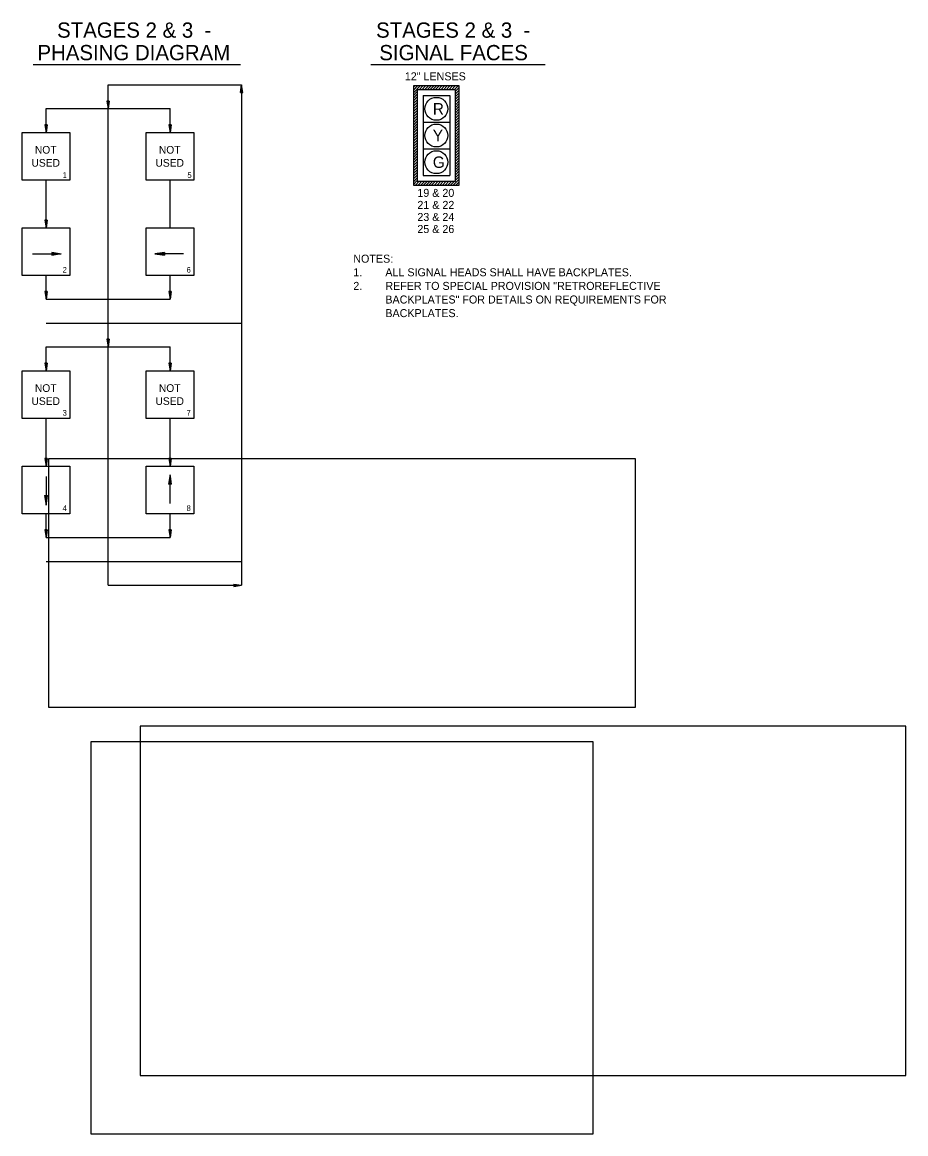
# Model space of a CAD drawing. Extents: x 418532 to 419834, y -565899 to -565282.
# Drawn here: x 418893 to 419356, y -565865 to -565282 of the extents above; entities that cross this region are included whole.
import ezdxf

# ---------------------------------------------------------------- set-up
doc = ezdxf.new("R2010")
doc.units = 0
for name, color, linetype in [('C-ANNO-TEXT', 7, 'Continuous'), ('Level 57', 7, 'Continuous'), ('Level 61', 7, 'Continuous'), ('T_Drafting', 7, 'Continuous'), ('Template', 7, 'Continuous'), ('V-SIGNAL-LOOP', 7, 'Continuous')]:
    doc.layers.add(name, color=color, linetype=linetype)

msp = doc.modelspace()

# ---------------------------------------------------------------- linework, layer by layer
at = {"layer": 'Level 57'}
for p, q in [((418898.43, -565304.08), (419007.1, -565304.08)), ((419075.35, -565304.08), (419166.69, -565304.08)), ((418937.63, -565577.29), (418937.63, -565314.79)), ((418937.63, -565314.79), (419007.63, -565314.79)), ((419007.03, -565318.79), (419007.63, -565314.79)), ((419007.63, -565314.79), (419007.63, -565577.29)), ((419008.23, -565318.79), (419007.63, -565314.79)), ((419007.03, -565318.79), (419008.23, -565318.79)), ((419007.13, -565318.79), (419007.63, -565315.46)), ((419007.23, -565318.79), (419007.63, -565316.15)), ((419007.33, -565318.79), (419007.63, -565316.81)), ((419007.43, -565318.79), (419007.63, -565317.49)), ((419007.53, -565318.79), (419007.63, -565318.16)), ((419008.13, -565318.79), (419007.63, -565315.46)), ((419008.02, -565318.79), (419007.63, -565316.15)), ((419007.92, -565318.79), (419007.63, -565316.81)), ((419007.82, -565318.79), (419007.63, -565317.49)), ((419007.72, -565318.79), (419007.63, -565318.16)), ((418937.03, -565323.29), (418937.63, -565327.29)), ((418938.23, -565323.29), (418937.03, -565323.29)), ((418937.13, -565323.29), (418937.63, -565326.62)), ((418937.23, -565323.29), (418937.63, -565325.94)), ((418937.33, -565323.29), (418937.63, -565325.27)), ((418937.43, -565323.29), (418937.63, -565324.59)), ((418937.53, -565323.29), (418937.63, -565323.92)), ((418938.23, -565323.29), (418937.63, -565327.29)), ((418937.82, -565323.29), (418937.63, -565324.59)), ((418938.02, -565323.29), (418937.63, -565325.94)), ((418938.13, -565323.29), (418937.63, -565326.62)), ((418937.92, -565323.29), (418937.63, -565325.27)), ((418937.72, -565323.29), (418937.63, -565323.92)), ((418905.13, -565339.79), (418905.13, -565327.29)), ((418905.13, -565327.29), (418970.13, -565327.29)), ((418970.13, -565339.79), (418970.13, -565327.29)), ((418904.53, -565335.79), (418905.13, -565339.79)), ((418905.73, -565335.79), (418904.53, -565335.79)), ((418904.63, -565335.79), (418905.13, -565339.12)), ((418904.73, -565335.79), (418905.13, -565338.44)), ((418904.83, -565335.79), (418905.13, -565337.77)), ((418904.93, -565335.79), (418905.13, -565337.09)), ((418905.03, -565335.79), (418905.13, -565336.42)), ((418905.73, -565335.79), (418905.13, -565339.79)), ((418905.32, -565335.79), (418905.13, -565337.09)), ((418905.52, -565335.79), (418905.13, -565338.44)), ((418905.63, -565335.79), (418905.13, -565339.12)), ((418905.42, -565335.79), (418905.13, -565337.77)), ((418905.22, -565335.79), (418905.13, -565336.42)), ((418969.53, -565335.79), (418970.13, -565339.79)), ((418970.73, -565335.79), (418969.53, -565335.79)), ((418969.63, -565335.79), (418970.13, -565339.12)), ((418969.73, -565335.79), (418970.13, -565338.44)), ((418969.83, -565335.79), (418970.13, -565337.77)), ((418969.93, -565335.79), (418970.13, -565337.09)), ((418970.03, -565335.79), (418970.13, -565336.42)), ((418970.73, -565335.79), (418970.13, -565339.79)), ((418970.32, -565335.79), (418970.13, -565337.09)), ((418970.52, -565335.79), (418970.13, -565338.44)), ((418970.63, -565335.79), (418970.13, -565339.12)), ((418970.42, -565335.79), (418970.13, -565337.77)), ((418970.22, -565335.79), (418970.13, -565336.42)), ((418905.13, -565389.79), (418905.13, -565364.79)), ((418970.13, -565389.79), (418970.13, -565364.79)), ((418904.53, -565385.79), (418905.13, -565389.79)), ((418905.73, -565385.79), (418904.53, -565385.79)), ((418904.63, -565385.79), (418905.13, -565389.12)), ((418904.73, -565385.79), (418905.13, -565388.44)), ((418904.83, -565385.79), (418905.13, -565387.77)), ((418904.93, -565385.79), (418905.13, -565387.09)), ((418905.03, -565385.79), (418905.13, -565386.42)), ((418905.73, -565385.79), (418905.13, -565389.79)), ((418905.32, -565385.79), (418905.13, -565387.09)), ((418905.52, -565385.79), (418905.13, -565388.44)), ((418905.63, -565385.79), (418905.13, -565389.12)), ((418905.42, -565385.79), (418905.13, -565387.77)), ((418905.22, -565385.79), (418905.13, -565386.42)), ((418898.06, -565403.45), (418913.06, -565403.46)), ((418908.06, -565402.71), (418913.06, -565403.46)), ((418908.06, -565402.71), (418908.06, -565404.21)), ((418912.23, -565403.46), (418908.06, -565402.83)), ((418908.06, -565402.96), (418911.37, -565403.46)), ((418910.54, -565403.46), (418908.06, -565403.09)), ((418908.06, -565403.22), (418909.69, -565403.46)), ((418908.85, -565403.46), (418908.06, -565403.34)), ((418913.06, -565403.46), (418908.06, -565404.21)), ((418908.06, -565404.08), (418912.23, -565403.46)), ((418911.37, -565403.46), (418908.06, -565403.96)), ((418908.06, -565403.83), (418910.54, -565403.46)), ((418909.69, -565403.46), (418908.06, -565403.7)), ((418908.06, -565403.58), (418908.85, -565403.46)), ((418967.19, -565402.71), (418962.19, -565403.46)), ((418977.19, -565403.45), (418962.19, -565403.46)), ((418962.19, -565403.46), (418967.19, -565404.21)), ((418963.02, -565403.46), (418967.19, -565402.83)), ((418967.19, -565404.08), (418963.02, -565403.46)), ((418967.19, -565402.96), (418963.88, -565403.46)), ((418963.88, -565403.46), (418967.19, -565403.96)), ((418964.72, -565403.46), (418967.19, -565403.09)), ((418967.19, -565403.83), (418964.72, -565403.46)), ((418967.19, -565403.22), (418965.56, -565403.46)), ((418965.56, -565403.46), (418967.19, -565403.7)), ((418966.4, -565403.46), (418967.19, -565403.34)), ((418967.19, -565403.58), (418966.4, -565403.46)), ((418967.19, -565402.71), (418967.19, -565404.21)), ((418905.13, -565427.29), (418905.13, -565414.79)), ((418970.13, -565427.29), (418970.13, -565414.79)), ((418970.13, -565427.29), (418970.13, -565414.79)), ((418904.53, -565423.29), (418905.13, -565427.29)), ((418905.73, -565423.29), (418904.53, -565423.29)), ((418904.63, -565423.29), (418905.13, -565426.62)), ((418904.73, -565423.29), (418905.13, -565425.94)), ((418904.83, -565423.29), (418905.13, -565425.27)), ((418904.93, -565423.29), (418905.13, -565424.59)), ((418905.03, -565423.29), (418905.13, -565423.92)), ((418905.73, -565423.29), (418905.13, -565427.29)), ((418905.32, -565423.29), (418905.13, -565424.59)), ((418905.52, -565423.29), (418905.13, -565425.94)), ((418905.63, -565423.29), (418905.13, -565426.62)), ((418905.42, -565423.29), (418905.13, -565425.27)), ((418905.22, -565423.29), (418905.13, -565423.92)), ((418969.53, -565423.29), (418970.13, -565427.29)), ((418970.73, -565423.29), (418969.53, -565423.29)), ((418969.53, -565423.29), (418970.13, -565427.29)), ((418970.73, -565423.29), (418969.53, -565423.29)), ((418969.63, -565423.29), (418970.13, -565426.62)), ((418969.63, -565423.29), (418970.13, -565426.62)), ((418969.73, -565423.29), (418970.13, -565425.94)), ((418969.73, -565423.29), (418970.13, -565425.94)), ((418969.83, -565423.29), (418970.13, -565425.27)), ((418969.83, -565423.29), (418970.13, -565425.27)), ((418969.93, -565423.29), (418970.13, -565424.59)), ((418969.93, -565423.29), (418970.13, -565424.59)), ((418970.03, -565423.29), (418970.13, -565423.92)), ((418970.03, -565423.29), (418970.13, -565423.92)), ((418970.73, -565423.29), (418970.13, -565427.29)), ((418970.32, -565423.29), (418970.13, -565424.59)), ((418970.52, -565423.29), (418970.13, -565425.94)), ((418970.63, -565423.29), (418970.13, -565426.62)), ((418970.42, -565423.29), (418970.13, -565425.27)), ((418970.22, -565423.29), (418970.13, -565423.92)), ((418970.73, -565423.29), (418970.13, -565427.29)), ((418970.32, -565423.29), (418970.13, -565424.59)), ((418970.52, -565423.29), (418970.13, -565425.94)), ((418970.63, -565423.29), (418970.13, -565426.62)), ((418970.42, -565423.29), (418970.13, -565425.27)), ((418970.22, -565423.29), (418970.13, -565423.92)), ((418905.13, -565427.29), (418970.13, -565427.29)), ((418905.13, -565439.79), (419007.63, -565439.79)), ((418937.03, -565448.29), (418937.63, -565452.29)), ((418938.23, -565448.29), (418937.03, -565448.29)), ((418937.13, -565448.29), (418937.63, -565451.62)), ((418937.23, -565448.29), (418937.63, -565450.94)), ((418937.33, -565448.29), (418937.63, -565450.27)), ((418937.43, -565448.29), (418937.63, -565449.59)), ((418937.53, -565448.29), (418937.63, -565448.92)), ((418938.23, -565448.29), (418937.63, -565452.29)), ((418937.82, -565448.29), (418937.63, -565449.59)), ((418938.02, -565448.29), (418937.63, -565450.94)), ((418938.13, -565448.29), (418937.63, -565451.62)), ((418937.92, -565448.29), (418937.63, -565450.27)), ((418937.72, -565448.29), (418937.63, -565448.92)), ((418905.13, -565452.29), (418970.13, -565452.29)), ((418905.13, -565464.79), (418905.13, -565452.29)), ((418970.13, -565464.79), (418970.13, -565452.29)), ((418904.53, -565460.79), (418905.13, -565464.79)), ((418905.73, -565460.79), (418904.53, -565460.79)), ((418904.63, -565460.79), (418905.13, -565464.12)), ((418904.73, -565460.79), (418905.13, -565463.44)), ((418904.83, -565460.79), (418905.13, -565462.77)), ((418904.93, -565460.79), (418905.13, -565462.09)), ((418905.03, -565460.79), (418905.13, -565461.42)), ((418905.73, -565460.79), (418905.13, -565464.79)), ((418905.32, -565460.79), (418905.13, -565462.09)), ((418905.52, -565460.79), (418905.13, -565463.44)), ((418905.63, -565460.79), (418905.13, -565464.12)), ((418905.42, -565460.79), (418905.13, -565462.77)), ((418905.22, -565460.79), (418905.13, -565461.42)), ((418969.53, -565460.79), (418970.13, -565464.79)), ((418970.73, -565460.79), (418969.53, -565460.79)), ((418969.63, -565460.79), (418970.13, -565464.12)), ((418969.73, -565460.79), (418970.13, -565463.44)), ((418969.83, -565460.79), (418970.13, -565462.77)), ((418969.93, -565460.79), (418970.13, -565462.09)), ((418970.03, -565460.79), (418970.13, -565461.42)), ((418970.73, -565460.79), (418970.13, -565464.79)), ((418970.32, -565460.79), (418970.13, -565462.09)), ((418970.52, -565460.79), (418970.13, -565463.44)), ((418970.63, -565460.79), (418970.13, -565464.12)), ((418970.42, -565460.79), (418970.13, -565462.77)), ((418970.22, -565460.79), (418970.13, -565461.42)), ((418905.13, -565514.79), (418905.13, -565489.79)), ((418970.13, -565514.79), (418970.13, -565489.79)), ((418904.53, -565510.79), (418905.13, -565514.79)), ((418905.73, -565510.79), (418904.53, -565510.79)), ((418904.63, -565510.79), (418905.13, -565514.12)), ((418904.73, -565510.79), (418905.13, -565513.44)), ((418904.83, -565510.79), (418905.13, -565512.77)), ((418904.93, -565510.79), (418905.13, -565512.09)), ((418905.03, -565510.79), (418905.13, -565511.42)), ((418905.73, -565510.79), (418905.13, -565514.79)), ((418905.32, -565510.79), (418905.13, -565512.09)), ((418905.52, -565510.79), (418905.13, -565513.44)), ((418905.63, -565510.79), (418905.13, -565514.12)), ((418905.42, -565510.79), (418905.13, -565512.77)), ((418905.22, -565510.79), (418905.13, -565511.42)), ((418969.53, -565510.79), (418970.13, -565514.79)), ((418970.73, -565510.79), (418969.53, -565510.79)), ((418969.63, -565510.79), (418970.13, -565514.12)), ((418969.73, -565510.79), (418970.13, -565513.44)), ((418969.83, -565510.79), (418970.13, -565512.77)), ((418969.93, -565510.79), (418970.13, -565512.09)), ((418970.03, -565510.79), (418970.13, -565511.42)), ((418970.73, -565510.79), (418970.13, -565514.79)), ((418970.32, -565510.79), (418970.13, -565512.09)), ((418970.52, -565510.79), (418970.13, -565513.44)), ((418970.63, -565510.79), (418970.13, -565514.12)), ((418970.42, -565510.79), (418970.13, -565512.77)), ((418970.22, -565510.79), (418970.13, -565511.42)), ((418905.12, -565520.23), (418905.13, -565535.23)), ((418970.12, -565519.36), (418969.37, -565524.36)), ((418970.87, -565524.36), (418969.37, -565524.36)), ((418969.5, -565524.36), (418970.12, -565520.19)), ((418970.12, -565521.05), (418969.62, -565524.36)), ((418969.75, -565524.36), (418970.12, -565521.88)), ((418970.12, -565522.73), (418969.88, -565524.36)), ((418970, -565524.36), (418970.12, -565523.57)), ((418970.13, -565534.36), (418970.12, -565519.36)), ((418970.87, -565524.36), (418970.12, -565519.36)), ((418970.12, -565520.19), (418970.75, -565524.36)), ((418970.62, -565524.36), (418970.12, -565521.05)), ((418970.12, -565521.88), (418970.49, -565524.36)), ((418970.36, -565524.36), (418970.12, -565522.73)), ((418970.12, -565523.57), (418970.24, -565524.36)), ((418904.38, -565530.23), (418905.13, -565535.23)), ((418904.38, -565530.23), (418905.88, -565530.23)), ((418905.13, -565534.4), (418904.5, -565530.23)), ((418904.63, -565530.23), (418905.13, -565533.54)), ((418905.13, -565532.7), (418904.76, -565530.23)), ((418904.89, -565530.23), (418905.13, -565531.86)), ((418905.13, -565531.02), (418905.01, -565530.23)), ((418905.13, -565535.23), (418905.88, -565530.23)), ((418905.75, -565530.23), (418905.13, -565534.4)), ((418905.13, -565533.54), (418905.63, -565530.23)), ((418905.5, -565530.23), (418905.13, -565532.7)), ((418905.13, -565531.86), (418905.37, -565530.23)), ((418905.25, -565530.23), (418905.13, -565531.02)), ((418905.13, -565552.29), (418905.13, -565539.79)), ((418970.13, -565552.29), (418970.13, -565539.79)), ((418904.53, -565548.29), (418905.13, -565552.29)), ((418905.73, -565548.29), (418904.53, -565548.29)), ((418904.63, -565548.29), (418905.13, -565551.62)), ((418904.73, -565548.29), (418905.13, -565550.94)), ((418904.83, -565548.29), (418905.13, -565550.27)), ((418904.93, -565548.29), (418905.13, -565549.59)), ((418905.03, -565548.29), (418905.13, -565548.92)), ((418905.73, -565548.29), (418905.13, -565552.29)), ((418905.32, -565548.29), (418905.13, -565549.59)), ((418905.52, -565548.29), (418905.13, -565550.94)), ((418905.63, -565548.29), (418905.13, -565551.62)), ((418905.42, -565548.29), (418905.13, -565550.27)), ((418905.22, -565548.29), (418905.13, -565548.92)), ((418969.53, -565548.29), (418970.13, -565552.29)), ((418970.73, -565548.29), (418969.53, -565548.29)), ((418969.63, -565548.29), (418970.13, -565551.62)), ((418969.73, -565548.29), (418970.13, -565550.94)), ((418969.83, -565548.29), (418970.13, -565550.27)), ((418969.93, -565548.29), (418970.13, -565549.59)), ((418970.03, -565548.29), (418970.13, -565548.92)), ((418970.73, -565548.29), (418970.13, -565552.29)), ((418970.32, -565548.29), (418970.13, -565549.59)), ((418970.52, -565548.29), (418970.13, -565550.94)), ((418970.63, -565548.29), (418970.13, -565551.62)), ((418970.42, -565548.29), (418970.13, -565550.27)), ((418970.22, -565548.29), (418970.13, -565548.92)), ((418905.13, -565552.29), (418970.13, -565552.29)), ((418905.13, -565564.79), (419007.63, -565564.79)), ((418937.63, -565577.29), (419007.63, -565577.29)), ((419003.63, -565576.69), (419007.63, -565577.29)), ((419003.63, -565576.69), (419003.63, -565577.89)), ((419003.63, -565576.79), (419006.96, -565577.29)), ((419003.63, -565576.89), (419006.27, -565577.29)), ((419003.63, -565576.99), (419005.6, -565577.29)), ((419003.63, -565577.1), (419004.93, -565577.29)), ((419003.63, -565577.2), (419004.26, -565577.29)), ((419003.63, -565577.89), (419007.63, -565577.29)), ((419003.63, -565577.49), (419004.93, -565577.29)), ((419003.63, -565577.69), (419006.27, -565577.29)), ((419003.63, -565577.79), (419006.96, -565577.29)), ((419003.63, -565577.59), (419005.6, -565577.29)), ((419003.63, -565577.39), (419004.26, -565577.29))]:
    msp.add_line(p, q, dxfattribs=at)
for points in [[(418892.63, -565339.79), (418917.63, -565339.79), (418917.63, -565364.79), (418892.63, -565364.79)], [(418957.63, -565339.79), (418982.63, -565339.79), (418982.63, -565364.79), (418957.63, -565364.79)], [(418892.63, -565389.79), (418917.63, -565389.79), (418917.63, -565414.79), (418892.63, -565414.79)], [(418957.63, -565389.79), (418982.63, -565389.79), (418982.63, -565414.79), (418957.63, -565414.79)], [(418892.63, -565464.79), (418917.63, -565464.79), (418917.63, -565489.79), (418892.63, -565489.79)], [(418957.63, -565464.79), (418982.63, -565464.79), (418982.63, -565489.79), (418957.63, -565489.79)], [(418892.63, -565514.79), (418917.63, -565514.79), (418917.63, -565539.79), (418892.63, -565539.79)], [(418957.63, -565514.79), (418982.63, -565514.79), (418982.63, -565539.79), (418957.63, -565539.79)]]:
    msp.add_lwpolyline(points, close=True, dxfattribs=at)
at = {"layer": 'T_Drafting'}
for p, q in [((419121.73, -565315.38), (419097.73, -565315.38)), ((419097.73, -565315.38), (419097.73, -565367.38)), ((419097.73, -565318.93), (419101.28, -565315.38)), ((419097.73, -565317.51), (419099.87, -565315.38)), ((419097.73, -565316.1), (419098.45, -565315.38)), ((419097.73, -565320.34), (419099.73, -565318.34)), ((419097.73, -565321.76), (419099.73, -565319.76)), ((419100.7, -565317.38), (419102.7, -565315.38)), ((419102.11, -565317.38), (419104.11, -565315.38)), ((419102.73, -565320.38), (419116.73, -565320.38)), ((419102.73, -565320.38), (419102.73, -565334.38)), ((419103.52, -565317.38), (419105.52, -565315.38)), ((419104.94, -565317.38), (419106.94, -565315.38)), ((419106.35, -565317.38), (419108.35, -565315.38)), ((419107.77, -565317.38), (419109.77, -565315.38)), ((419109.18, -565317.38), (419111.18, -565315.38)), ((419110.6, -565317.38), (419112.6, -565315.38)), ((419112.01, -565317.38), (419114.01, -565315.38)), ((419113.42, -565317.38), (419115.42, -565315.38)), ((419114.84, -565317.38), (419116.84, -565315.38)), ((419116.25, -565317.38), (419118.25, -565315.38)), ((419116.73, -565320.38), (419116.73, -565334.38)), ((419117.67, -565317.38), (419119.67, -565315.38)), ((419119.08, -565317.38), (419121.08, -565315.38)), ((419119.73, -565318.14), (419121.73, -565316.14)), ((419119.73, -565319.56), (419121.73, -565317.56)), ((419119.73, -565320.97), (419121.73, -565318.97)), ((419119.73, -565322.38), (419121.73, -565320.38)), ((419121.73, -565367.38), (419121.73, -565315.38)), ((419097.73, -565323.17), (419099.73, -565321.17)), ((419097.73, -565324.59), (419099.73, -565322.59)), ((419097.73, -565326), (419099.73, -565324)), ((419097.73, -565327.41), (419099.73, -565325.41)), ((419119.73, -565323.8), (419121.73, -565321.8)), ((419119.73, -565325.21), (419121.73, -565323.21)), ((419119.73, -565326.63), (419121.73, -565324.63)), ((419119.73, -565328.04), (419121.73, -565326.04)), ((419097.73, -565328.83), (419099.73, -565326.83)), ((419097.73, -565330.24), (419099.73, -565328.24)), ((419097.73, -565331.66), (419099.73, -565329.66)), ((419097.73, -565333.07), (419099.73, -565331.07)), ((419097.73, -565334.48), (419099.73, -565332.48)), ((419119.73, -565329.46), (419121.73, -565327.46)), ((419119.73, -565330.87), (419121.73, -565328.87)), ((419119.73, -565332.28), (419121.73, -565330.28)), ((419119.73, -565333.7), (419121.73, -565331.7)), ((419097.73, -565335.9), (419099.73, -565333.9)), ((419097.73, -565337.31), (419099.73, -565335.31)), ((419097.73, -565338.73), (419099.73, -565336.73)), ((419097.73, -565340.14), (419099.73, -565338.14)), ((419102.73, -565334.38), (419116.73, -565334.38)), ((419102.73, -565334.38), (419102.73, -565348.38)), ((419116.73, -565334.38), (419116.73, -565348.38)), ((419119.73, -565335.11), (419121.73, -565333.11)), ((419119.73, -565336.53), (419121.73, -565334.53)), ((419119.73, -565337.94), (419121.73, -565335.94)), ((419119.73, -565339.35), (419121.73, -565337.35)), ((419097.73, -565341.56), (419099.73, -565339.56)), ((419097.73, -565342.97), (419099.73, -565340.97)), ((419097.73, -565344.38), (419099.73, -565342.38)), ((419097.73, -565345.8), (419099.73, -565343.8)), ((419119.73, -565340.77), (419121.73, -565338.77)), ((419119.73, -565342.18), (419121.73, -565340.18)), ((419119.73, -565343.6), (419121.73, -565341.6)), ((419119.73, -565345.01), (419121.73, -565343.01)), ((419097.73, -565347.21), (419099.73, -565345.21)), ((419097.73, -565348.63), (419099.73, -565346.63)), ((419097.73, -565350.04), (419099.73, -565348.04)), ((419097.73, -565351.46), (419099.73, -565349.46)), ((419102.73, -565348.38), (419116.73, -565348.38)), ((419102.73, -565348.38), (419102.73, -565362.38)), ((419116.73, -565348.38), (419116.73, -565362.38)), ((419119.73, -565346.43), (419121.73, -565344.43)), ((419119.73, -565347.84), (419121.73, -565345.84)), ((419119.73, -565349.25), (419121.73, -565347.25)), ((419119.73, -565350.67), (419121.73, -565348.67)), ((419119.73, -565352.08), (419121.73, -565350.08)), ((419097.73, -565352.87), (419099.73, -565350.87)), ((419097.73, -565354.28), (419099.73, -565352.28)), ((419097.73, -565355.7), (419099.73, -565353.7)), ((419097.73, -565357.11), (419099.73, -565355.11)), ((419119.73, -565353.5), (419121.73, -565351.5)), ((419119.73, -565354.91), (419121.73, -565352.91)), ((419119.73, -565356.33), (419121.73, -565354.33)), ((419119.73, -565357.74), (419121.73, -565355.74)), ((419097.73, -565358.53), (419099.73, -565356.53)), ((419097.73, -565359.94), (419099.73, -565357.94)), ((419097.73, -565361.35), (419099.73, -565359.35)), ((419097.73, -565362.77), (419099.73, -565360.77)), ((419119.73, -565359.15), (419121.73, -565357.15)), ((419119.73, -565360.57), (419121.73, -565358.57)), ((419119.73, -565361.98), (419121.73, -565359.98)), ((419119.73, -565363.4), (419121.73, -565361.4)), ((419097.73, -565364.18), (419099.73, -565362.18)), ((419097.73, -565365.6), (419099.73, -565363.6)), ((419097.73, -565367.01), (419099.73, -565365.01)), ((419097.73, -565367.38), (419121.73, -565367.38)), ((419098.78, -565367.38), (419100.78, -565365.38)), ((419100.19, -565367.38), (419102.19, -565365.38)), ((419101.61, -565367.38), (419103.61, -565365.38)), ((419102.73, -565362.38), (419116.73, -565362.38)), ((419103.02, -565367.38), (419105.02, -565365.38)), ((419104.44, -565367.38), (419106.44, -565365.38)), ((419105.85, -565367.38), (419107.85, -565365.38)), ((419107.26, -565367.38), (419109.26, -565365.38)), ((419108.68, -565367.38), (419110.68, -565365.38)), ((419110.09, -565367.38), (419112.09, -565365.38)), ((419111.51, -565367.38), (419113.51, -565365.38)), ((419112.92, -565367.38), (419114.92, -565365.38)), ((419114.34, -565367.38), (419116.34, -565365.38)), ((419115.75, -565367.38), (419117.75, -565365.38)), ((419117.16, -565367.38), (419119.16, -565365.38)), ((419118.58, -565367.38), (419121.73, -565364.22)), ((419119.73, -565364.81), (419121.73, -565362.81)), ((419119.99, -565367.38), (419121.73, -565365.64)), ((419121.41, -565367.38), (419121.73, -565367.05))]:
    msp.add_line(p, q, dxfattribs=at)
msp.add_lwpolyline([(419119.73, -565365.38), (419119.73, -565317.38), (419099.73, -565317.38), (419099.73, -565365.38)], close=True, dxfattribs=at)
for centre in [(419109.73, -565327.38), (419109.73, -565341.38), (419109.73, -565355.38)]:
    msp.add_circle(centre, 6, dxfattribs=at)
at = {"layer": 'Template'}
for points in [[(419214.2, -565511.02), (418906.32, -565511.02), (418906.32, -565641.34), (419214.2, -565641.34)], [(419191.97, -565659.48), (418928.54, -565659.48), (418928.54, -565865.04), (419191.97, -565865.04)]]:
    msp.add_lwpolyline(points, close=True, dxfattribs=at)
at = {"layer": 'V-SIGNAL-LOOP'}
msp.add_lwpolyline([(418954.41, -565834.55), (419355.8, -565834.55), (419355.8, -565651.22), (418954.41, -565651.22)], close=True, dxfattribs=at)

# ---------------------------------------------------------------- texts
at = {"layer": 'C-ANNO-TEXT'}
for s, p in [('19 & 20', (419099.76, -565373.57)), ('21 & 22', (419099.78, -565379.89)), ('23 & 24', (419099.77, -565386.21)), ('25 & 26', (419099.76, -565392.53)), ('NOTES:', (419066.18, -565408.09)), ('1.', (419066.18, -565415.23)), ('ALL SIGNAL HEADS SHALL HAVE BACKPLATES.', (419082.98, -565415.23)), ('2.', (419066.18, -565422.37)), ('REFER TO SPECIAL PROVISION "RETROREFLECTIVE', (419082.98, -565422.37)), ('BACKPLATES" FOR DETAILS ON REQUIREMENTS FOR ', (419082.98, -565429.51)), ('BACKPLATES.', (419082.98, -565436.65))]:
    msp.add_text(s, height=4.2, rotation=360, dxfattribs=at).set_placement(p)
at = {"layer": 'Level 57'}
for s, height, p in [('STAGES 2 & 3  - ', 8, (418910.91, -565290.08)), ('STAGES 2 & 3  - ', 8, (419078.14, -565290.08)), ('PHASING DIAGRAM', 8, (418900.6, -565301.9)), ('SIGNAL FACES', 8, (419079.81, -565301.9)), ('NOT', 4.025, (418899.25, -565350.88)), ('NOT', 4.025, (418964.25, -565350.88)), ('USED', 4.025, (418897.46, -565357.73)), ('USED', 4.025, (418962.46, -565357.73)), ('1', 3, (418913.78, -565363.65)), ('5', 3, (418979.19, -565363.65)), ('2', 3, (418913.78, -565413.37)), ('6', 3, (418978.78, -565413.37)), ('NOT', 4.025, (418899.25, -565475.88)), ('NOT', 4.025, (418964.25, -565475.88)), ('USED', 4.025, (418897.46, -565482.73)), ('USED', 4.025, (418962.46, -565482.73)), ('3', 3, (418913.78, -565488.37)), ('7', 3, (418978.78, -565488.37)), ('4', 3, (418913.78, -565538.37)), ('8', 3, (418978.78, -565538.37))]:
    msp.add_text(s, height=height, dxfattribs=at).set_placement(p)
at = {"layer": 'Level 61'}
msp.add_text('12" LENSES', height=4.2, dxfattribs=at).set_placement((419093.19, -565312.44))
at = {"layer": 'T_Drafting'}
for s, p in [('R', (419107.87, -565330.38)), ('Y', (419107.85, -565344.38)), ('G', (419107.87, -565358.38))]:
    msp.add_text(s, height=6, dxfattribs=at).set_placement(p)

doc.saveas('drawing.dxf')
